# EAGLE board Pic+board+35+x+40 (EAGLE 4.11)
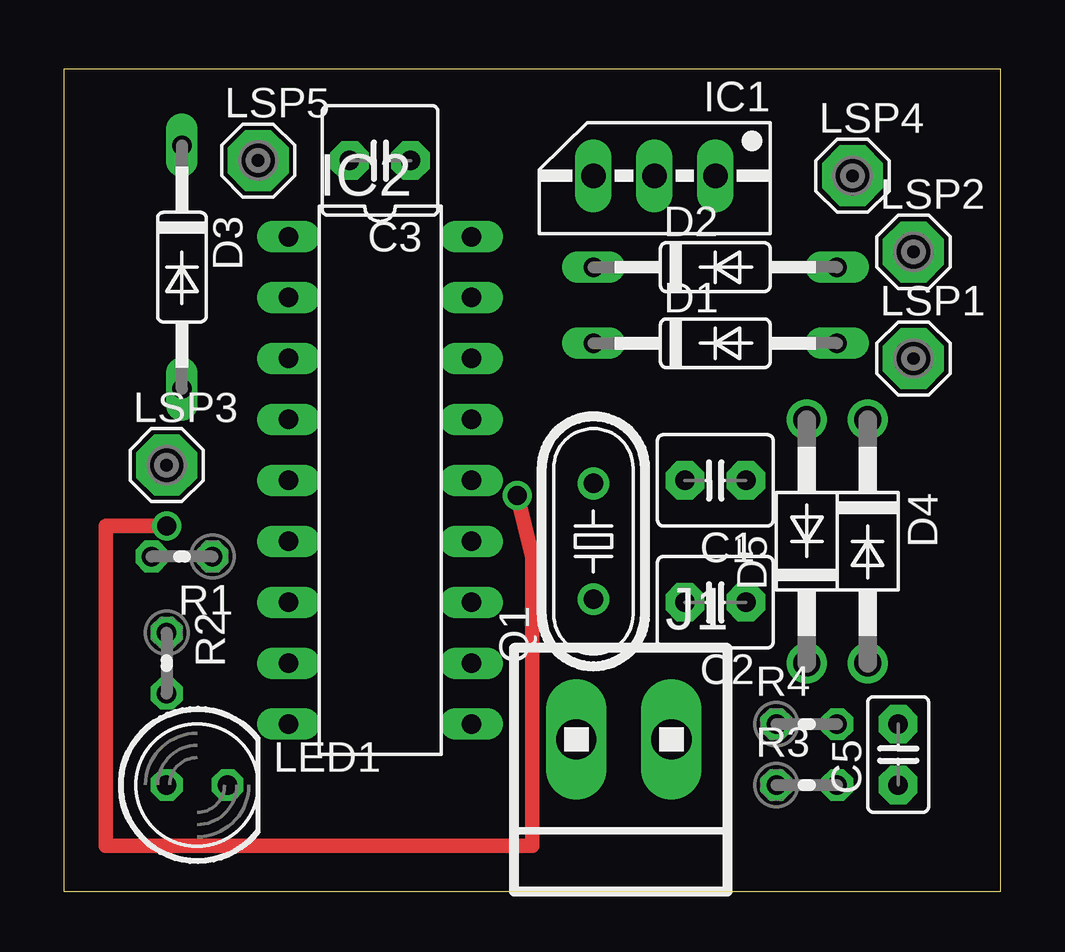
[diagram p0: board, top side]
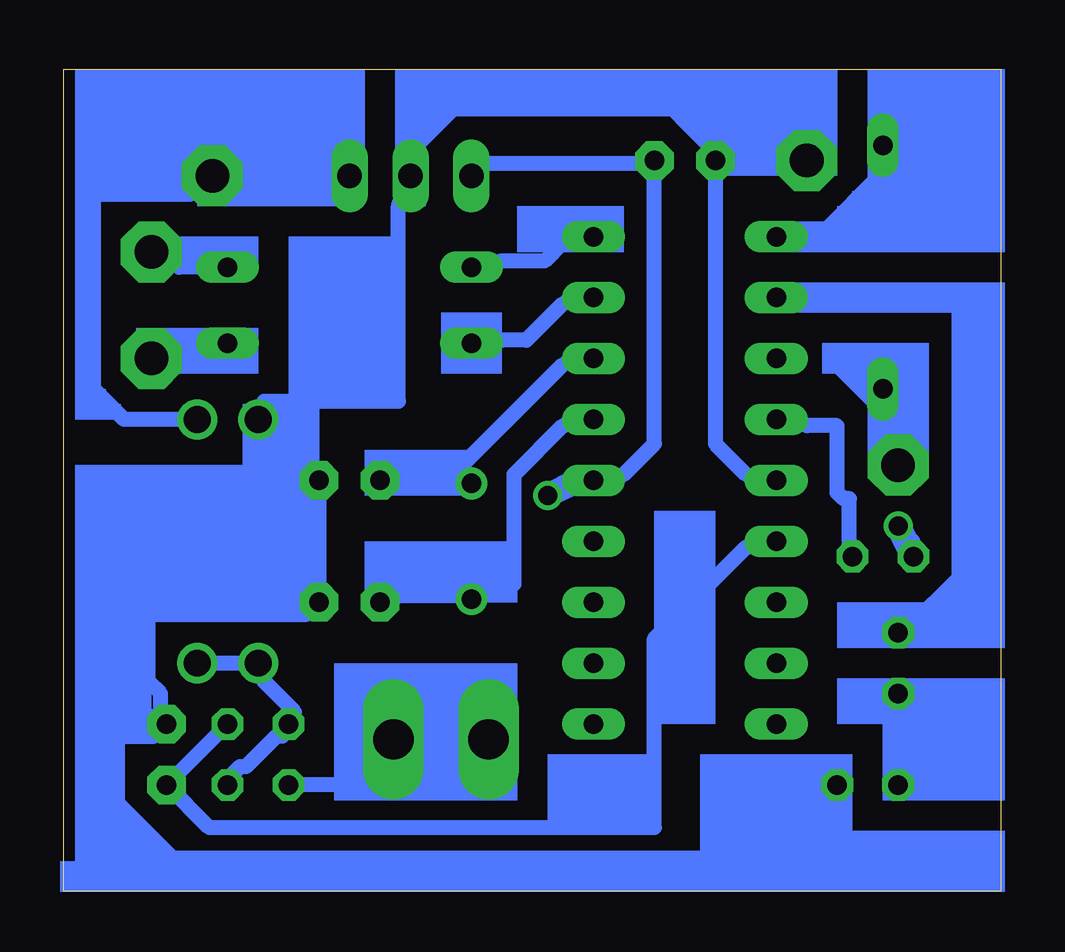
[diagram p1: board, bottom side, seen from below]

Size 39.04 x 34.28 mm. Coordinates in mm from the lower left corner, seen from the top.
Outline: 0,0 39.04,0 39.04,34.28 0,34.28 0,0
Copper layers (1*16): Top 0.035mm / dielectric 1.5mm / Bottom 0.035mm
Design rules "default": minimum track width 25mil, minimum drill 24mil, track to track 25mil, track to pad 30mil, pad to pad 30mil, via to via 30mil, smd to smd 8mil, copper to edge 40mil, drill to drill 8mil, minimum pad ring 10mil, minimum via ring 8mil, stop-mask expansion 4mil, vias tented up to drill 0mil, thermal gap 10mil

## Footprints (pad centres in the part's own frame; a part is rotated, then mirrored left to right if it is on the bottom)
C2.5-4 = drill 0.813 pad 1.6 octagon: 1 -1.27,0; 2 1.27,0
C2.5-5 = drill 0.813 pad 1.6 octagon: 1 -1.27,0; 2 1.27,0
C2.5-2 = drill 0.813 pad 1.6 octagon: 1 -1.27,0; 2 1.27,0
DO35-10 = drill 0.813 long: A 5.08,0; C -5.08,0
DO41-10 = drill 1.118 round: A 5.08,0; C -5.08,0
78MXXS = drill 1.016 long: GND 0,-2.54; IN -2.54,-2.54; OUT 2.54,-2.54
DIL18 = drill 0.813 long: 1 -10.16,-3.81; 2 -7.62,-3.81; 3 -5.08,-3.81; 4 -2.54,-3.81; 5 0,-3.81; 6 2.54,-3.81; 7 5.08,-3.81; 8 7.62,-3.81; 9 10.16,-3.81; 10 10.16,3.81; 11 7.62,3.81; 12 5.08,3.81; 13 2.54,3.81; 14 0,3.81; 15 -2.54,3.81; 16 -5.08,3.81; 17 -7.62,3.81; 18 -10.16,3.81
1X2MTA = drill 1.676 long: 1 1.981,0; 2 -1.981,0
LED5MM = drill 0.813 octagon: A -1.27,0; K 1.27,0
SE14 = drill 1.397 pad 2.54 octagon: MP 0,0
HC49/S = drill 0.813 round: 1 -2.413,0; 2 2.413,0
0204V = drill 0.813 octagon: 1 -1.27,0; 2 1.27,0

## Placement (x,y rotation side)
C1  22pF  [C2.5-4]  27.14,17.14 180 top
C2  [C2.5-4]  27.14,12.06 180 top
C3  22uF  [C2.5-5]  13.17,30.48 180 top
C5  22pF  [C2.5-2]  34.76,5.71 90 top
D1  1N4148  [DO35-10]  27.14,22.86 0 top
D2  1N4148  [DO35-10]  27.14,26.03 0 top
D3  1N4148  [DO35-10]  4.91,26.03 270 top
D4  1N4004  [DO41-10]  33.49,14.6 270 top
D5  1N4004  [DO41-10]  30.95,14.6 90 top
IC1  7805  [78MXXS]  24.6,27.3 180 top
IC2  PIC16F84AP  [DIL18]  13.17,17.14 270 top
J1  [1X2MTA]  23.33,6.34 180 top
LED1  [LED5MM]  5.55,4.44 0 top
LSP1  SE14  [SE14]  35.4,22.22 0 top
LSP2  SE14  [SE14]  35.4,26.66 0 top
LSP3  SE14  [SE14]  4.28,17.77 0 top
LSP4  SE14  [SE14]  32.85,29.84 0 top
LSP5  SE14  [SE14]  8.09,30.48 0 top
Q1  4 MHZ  [HC49/S]  22.06,14.6 90 top
R1  1K  [0204V]  4.91,13.96 180 top
R2  1K  [0204V]  4.28,9.52 270 top
R3  100K  [0204V]  30.95,4.44 0 top
R4  10K  [0204V]  30.95,6.98 0 top

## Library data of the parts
C1-C3 C5 = capacitor-wima
D1-D5 = diode
IC1 = v-reg
IC2 = microchip
J1 = con-amp
LED1 = led
LSP1-LSP5 = solpad
Q1 = crystal
R1-R4 = rcl

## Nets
GND: C1.1 C2.1 C3.2 C5.2 D5.A IC1.GND IC2.5 LED1.K LSP5.MP
N$1: D2.A LSP2.MP
N$4: D4.C IC1.IN LSP4.MP
N$6: D1.A LSP1.MP
N$8: D3.A LSP3.MP
N$9: IC2.4 R1.1
N$10: D1.C IC2.17
N$14: LED1.A R2.2
N$19: C2.2 IC2.15 Q1.1
N$24: J1.1 J1.2 R3.1
N$26: D3.C IC2.1
N$27: IC2.2 R2.1
N$28: IC2.3
N$30: IC2.7
N$31: IC2.8
N$32: IC2.9
N$33: IC2.10
N$34: IC2.11
N$35: IC2.12
N$36: IC2.13
N$37: C1.2 IC2.16 Q1.2
N$39: D2.C IC2.18
N$41: C5.1 IC2.6 R4.2
N$45: D4.A D5.C R3.2 R4.1
VCC: C3.1 IC1.OUT IC2.14 R1.2

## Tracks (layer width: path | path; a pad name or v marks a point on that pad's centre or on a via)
GND
  Bottom 0.635: LED1.K 7.33,4.19 10.12,1.39 34.51,1.39 36.79,3.68 36.79,6.47 35.27,6.47 C5.2 35.01,7.74 35.01,8.25 35.52,8.76 35.52,11.55 28.92,11.55 C2.1 C1.1 29.17,17.39 30.7,18.92 D5.A 30.7,20.44 25.11,20.44 25.11,28.57 IC1.GND 24.35,31.11 22.82,32.63 13.68,32.63 12.15,31.11 C3.2 | IC2.5 10.63,17.39 11.9,18.66 C3.2 | LSP5.MP 9.11,30.6 11.14,30.6 C3.2
N$1
  Bottom 0.635: D2.A 34.25,26.03 LSP2.MP
N$4
  Bottom 0.635: IC1.IN LSP4.MP 33.74,29.08 37.81,29.08 37.81,20.95 36.54,19.68 D4.C
N$6
  Bottom 0.635: D1.A 33.49,22.73 34.25,22.73 LSP1.MP
N$8
  Bottom 0.635: D3.A 4.79,19.68 4.79,18.92 LSP3.MP
N$9
  Bottom 0.635: R1.1 6.31,14.6 6.31,16.38 6.57,16.38 6.82,16.63 6.82,19.43 8.09,19.43 IC2.4
N$10
  Bottom 0.635: IC2.17 18.25,24.51 19.77,22.98 20.79,22.98 D1.C
N$14
  Bottom 0.635: LED1.A R2.2
N$19
  Bottom 0.635: C2.2 25.11,12.31 22.57,12.31 Q1.1 21.81,12.82 20.28,12.82 20.28,17.39 18.25,19.43 IC2.15
N$24
  Bottom 0.635: R3.1 26.38,4.44 J1.2 24.09,6.47 22.57,6.47 J1.1
N$26
  Bottom 0.635: D3.C 5.04,29.84 7.33,27.55 8.09,27.55 IC2.1
N$27
  Bottom 0.635: R2.1 3.77,11.04 1.74,13.08 1.74,24.51 8.09,24.51 IC2.2
N$37
  Bottom 0.635: 22.7,17.52 22.82,17.39 25.11,17.39 C1.2 | 22.7,17.52 18.25,21.97 IC2.16 | Q1.2 22.57,17.39 22.7,17.52
N$39
  Bottom 0.635: IC2.18 18.25,27.05 19.01,26.28 20.79,26.28 D2.C
N$41
  Bottom 0.61: C5.1 R4.2
  Bottom 0.635: IC2.6 10.63,14.35 14.44,10.54 14.44,2.66 32.98,2.66 C5.1
N$45
  Bottom 0.635: D4.A D5.C 30.7,8.76 29.43,7.49 R4.1 29.93,6.47 30.19,6.47 31.46,5.2 31.71,5.2 31.97,4.95 R3.2
S$1
  Bottom 1.016: 10.63,31.11 13.17,33.65 13.17,32.38 11.9,31.11 10.63,32.38
S$2
  Bottom 1.016: 6.82,22.22 4.28,19.68
VCC  (via drill 0.8)
  Top 0.61: v4.28,15.23 1.74,15.23 1.74,1.9 19.52,1.9 19.52,13.96 v18.88,16.5
  Bottom 0.61: R1.2 3.65,14.6 v4.28,15.23
  Bottom 0.635: IC1.OUT 21.55,30.35 15.2,30.35 C3.1 14.44,18.66 15.71,17.39 IC2.14 18.25,16.89 18.23,16.84
  Bottom 1.016: v4.28,15.23 R1.2 | v18.88,16.5 18.23,16.84 17.62,17.14
(copper drawn outside any net)
  shapes: Bottom area x65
